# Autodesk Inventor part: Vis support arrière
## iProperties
Shininess: 20.0
Angle Display Precision: 2
Document Length Units: 11269
Document Angle Units: 11279
Document Time Units: 11290
Document Mass Units: 11283
Document Length Units Precision: 3
Document Angle Units Precision: 2
Created: 2002-09
Part Number: Vis support arrière
Material: Par défaut
Document SubType Name: Modélisation
Designer: administrateur
Density: 0.0
Volumn: 0.0
Area: 0.0
PropertySet Name: Model Information
Control State: 0
Master: False
Checked Out: False
Author: administrateur
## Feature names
1. Extrusion1
2. Extrusion2
3. Extrusion3
4. Extrusion4
5. Chanfrein1 [Chamfer]
6. Chanfrein2 [Chamfer]
